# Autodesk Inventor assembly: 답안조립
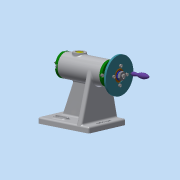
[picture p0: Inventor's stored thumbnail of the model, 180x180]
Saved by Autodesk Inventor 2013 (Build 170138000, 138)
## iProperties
Created: 2019-10
Part Number: 답안조립
Document SubType Name: Assembly
Designer: Administrator
Author: Administrator
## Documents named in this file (18)
- C:\Users\Administrator\Desktop\491004V1018\답안조립.iam
- C:\Users\Administrator\Desktop\491004V1018\본체.ipt
- C:\Users\Administrator\Desktop\491004V1018\나사.ipt
- C:\Users\Administrator\Desktop\491004V1018\나사축.ipt
- C:\Users\Administrator\Desktop\491004V1018\너트 M8.ipt
- C:\Users\Administrator\Desktop\491004V1018\돌림판.ipt
- C:\Users\Administrator\Desktop\491004V1018\멈춤나사 M3.ipt
- C:\Users\Administrator\Desktop\491004V1018\볼트 M3.ipt
- C:\Users\Administrator\Desktop\491004V1018\부시.ipt
- C:\Users\Administrator\Desktop\491004V1018\센터.ipt
- C:\Users\Administrator\Desktop\491004V1018\센터홀더.ipt
- C:\Users\Administrator\Desktop\491004V1018\슬리브.ipt
- C:\Users\Administrator\Desktop\491004V1018\와셔.ipt
- C:\Users\Administrator\Desktop\491004V1018\중공축.ipt
- C:\Users\Administrator\Desktop\491004V1018\커버.ipt
- C:\Users\Administrator\Desktop\491004V1018\키 4 x 4 x 10.ipt
- C:\Users\Administrator\Desktop\491004V1018\플랜지.ipt
- C:\Users\Administrator\Desktop\491004V1018\핸들.ipt
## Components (2 placed, 2 different names)
1. 플랜지:1
2. 핸들:1
